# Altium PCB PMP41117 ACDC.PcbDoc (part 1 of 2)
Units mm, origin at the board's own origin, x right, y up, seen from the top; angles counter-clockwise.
Board outline 48.82 x 27.36 mm, 2 copper layers (Top Layer, Bottom Layer), stack 1.016 mm thick; 59 components, 38 nets, 168 pads, 388 vias.
Unrouted connection lines stored in the file: 2.
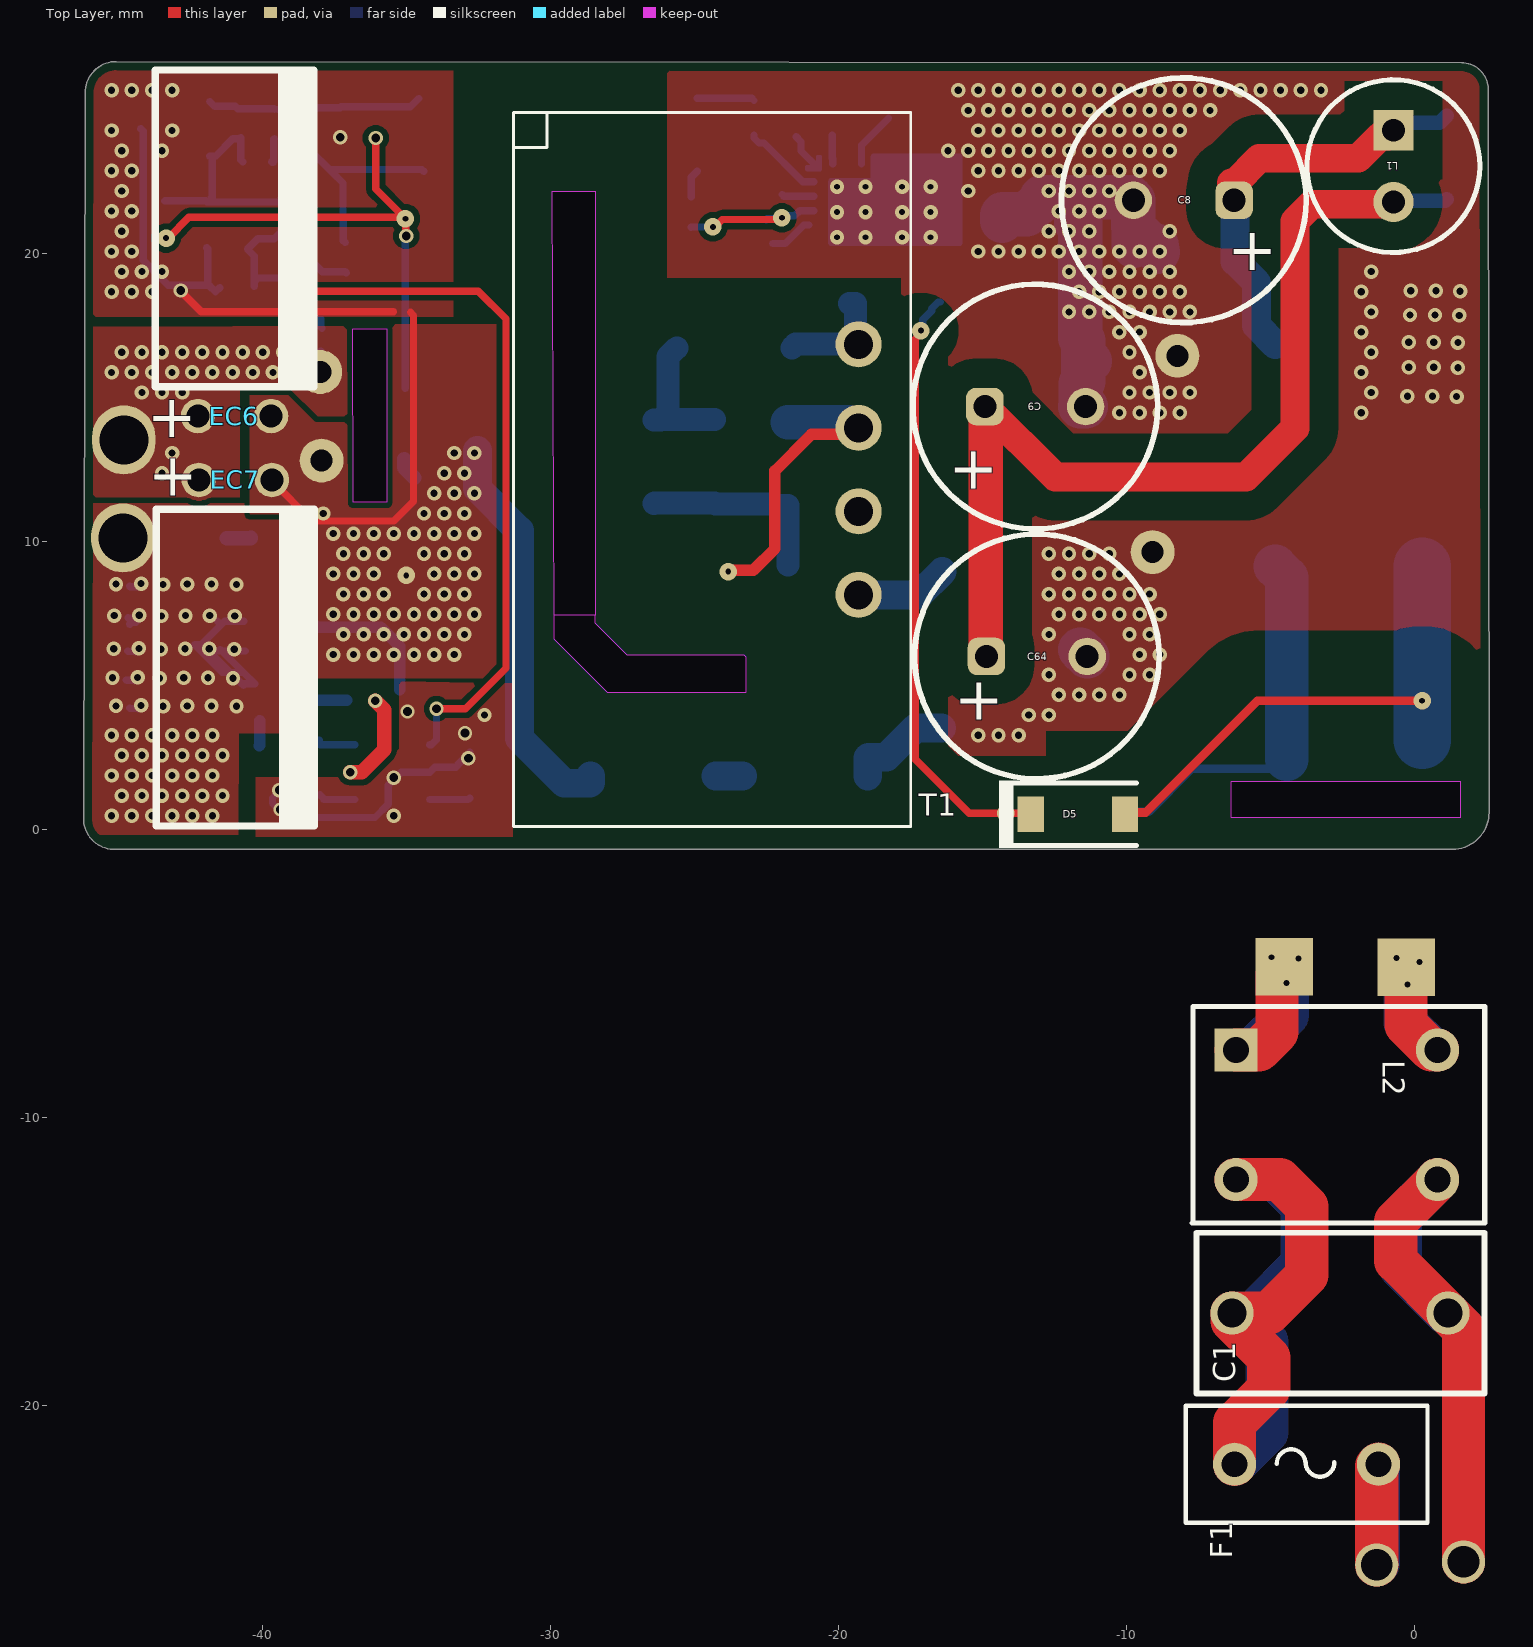
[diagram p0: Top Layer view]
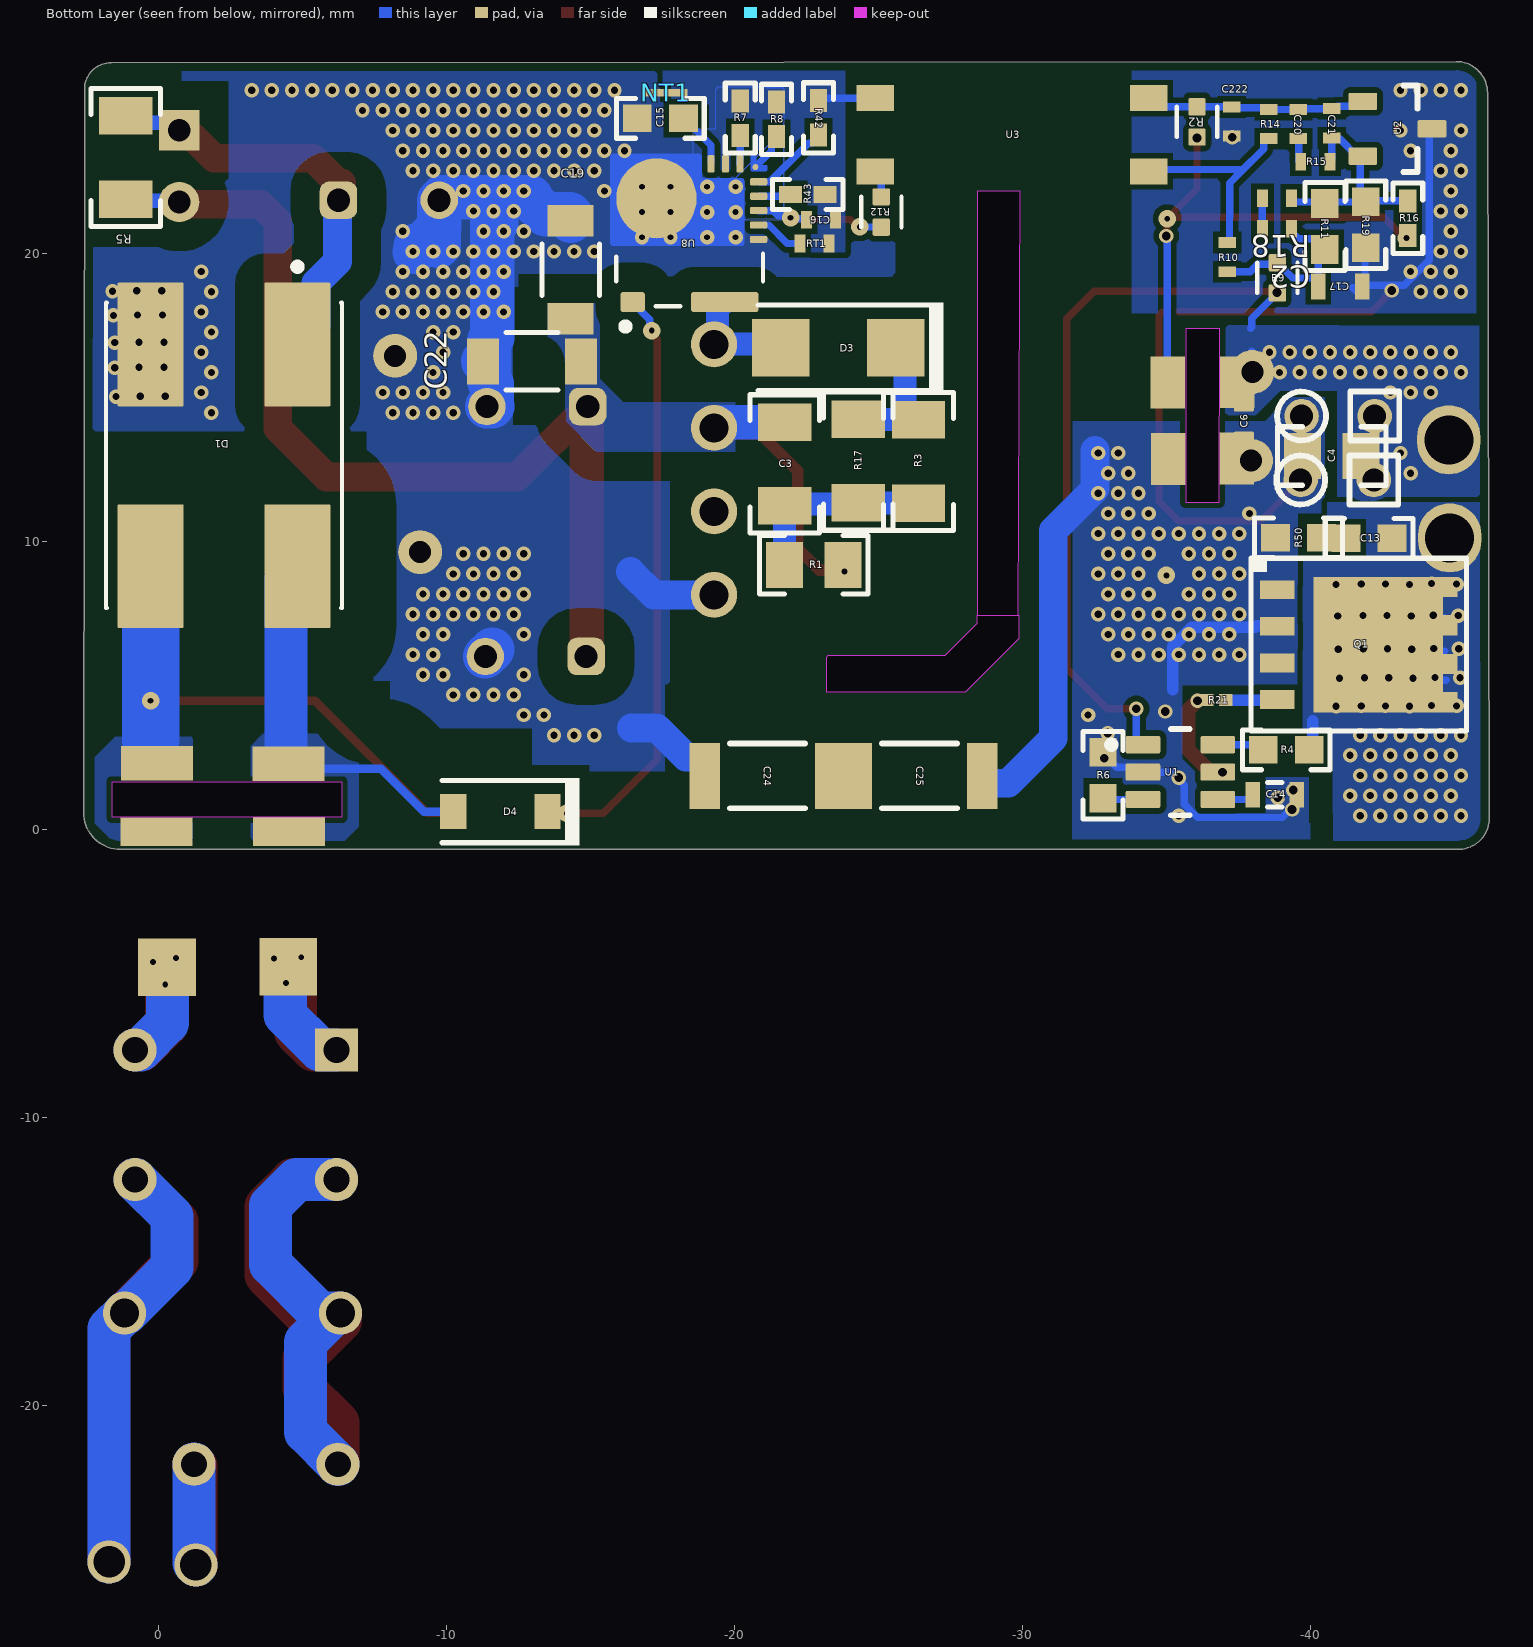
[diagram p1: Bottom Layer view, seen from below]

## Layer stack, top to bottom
Top Solder: solder mask 0.0102, Solder Resist, Dk 3.5
Top Layer: signal copper 0.0711
Dielectric1: core 0.8738, FR-4 High Tg, Dk 4.8
Bottom Layer: signal copper 0.0711
Bottom Solder: solder mask 0.0102, Solder Resist, Dk 3.5

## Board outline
-45.202,-0.676 cw(c-45.155,0.387) -46.208,0.234 -46.219,0.27 -46.164,25.595 cw(c-45.075,25.595) -45.075,26.684 1.643,26.644 cw(c1.643,25.723) 2.564,25.723 2.599,0.602 cw(c1.317,0.602) 1.318,-0.679 1.29,-0.679
cut-out: -6.376,1.665 -6.376,0.435 1.606,0.435 1.606,1.665
cut-out: -29.885,7.455 -29.885,6.63 -28.025,4.77 -23.21,4.77 -23.21,6 -23.27,6.06 -27.335,6.06 -28.445,7.17 -28.445,7.47
cut-out: -35.685,11.37 -36.846,11.37 -36.872,17.4 -35.685,17.4
cut-out: -28.445,7.455 -29.869,7.455 -29.931,22.185 -28.445,22.185 -28.445,19.53

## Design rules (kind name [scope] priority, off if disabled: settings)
AcuteAngle [All] p1: minimum=4.50000000000000E+0001 checktracksonly=FALSE
AssemblyTestPointUsage [All] p1: valid=2
BoardOutlineClearance BoardOutlineClearance_MountingHoles [OnCopper and InComponentClass('Mounting Holes')] p1: gap=0.3 ignorepadtopadclearanceinfootprint=FALSE
BoardOutlineClearance BoardOutlineClearance_Poly [OnCopper and IsPoly] p2: gap=0.3 ignorepadtopadclearanceinfootprint=FALSE
BoardOutlineClearance [OnCopper and Not InComponentClass('Logo') and not InComponentClass('FiducialMark') and not InRegion(1000,500,4000,800) and not InPoly] p3: gap=0.3 ignorepadtopadclearanceinfootprint=FALSE
Clearance Clearance_VAC_PGND [InNetClass('VAC') vs InNetClass('PGND')] p1: gap=2.286 ignorepadtopadclearanceinfootprint=TRUE
Clearance Clearance_HV_PGND [InNetClass('High Voltage') vs InNetClass('PGND')] p2: gap=1.016 ignorepadtopadclearanceinfootprint=TRUE
Clearance Clearance_SW_PGND [InNetClass('Switch Node') vs InNetClass('PGND')] p3: gap=0.864 ignorepadtopadclearanceinfootprint=TRUE
Clearance Clearance_AC_AC [InNetClass('VAC') vs InNetClass('VAC')] p4: gap=1 ignorepadtopadclearanceinfootprint=TRUE
Clearance Clearance_PGND_SGND [InNetClass('PGND') vs InNetClass('SGND')] p5: gap=4.064 ignorepadtopadclearanceinfootprint=TRUE
Clearance Clearance_HV_LV [InNetClass('High Voltage') vs InNetClass('Low Voltage')] p6: gap=0.864 ignorepadtopadclearanceinfootprint=TRUE
Clearance Clearance_SW_LV_1 [InNetClass('Switch Node') vs InNetClass('Low Voltage')] p7: gap=0.864 ignorepadtopadclearanceinfootprint=TRUE
Clearance Clearance_SW_HV [InNetClass('Switch Node') vs InNetClass('High Voltage')] p8: gap=0.864 ignorepadtopadclearanceinfootprint=TRUE
Clearance Clearance_1 [All] p9: gap=0.198 ignorepadtopadclearanceinfootprint=TRUE
Clearance Clearance_Keepouts [((IsTrack Or IsArc) And Not InPoly) And IsFree and IsKeepOut vs ((IsTrack Or IsArc) And Not InPoly) And IsFree and IsKeepOut] p10: gap=0 ignorepadtopadclearanceinfootprint=FALSE
Clearance Clearance_Poly [InPolygon] p11: gap=0.254 ignorepadtopadclearanceinfootprint=TRUE
Clearance Clearance_FiducialMark [IsKeepOut and InComponentClass('FiducialMark') vs IsPad and InComponentClass('FiducialMark')] p12: gap=0 ignorepadtopadclearanceinfootprint=FALSE
ComponentClearance ComponentClearance_MountingHoles_FiducialMarks [InComponentClass('Mounting Holes') vs InComponentClass('FiducialMark')] p1: gap=0.2 collisioncheckmode=3 verticalgap=0.2 showdistances=FALSE
ComponentClearance ComponentClearance_Shunt [InComponentClass('Header') vs InComponentClass('Shunt')] p2: gap=0 collisioncheckmode=3 verticalgap=0 showdistances=FALSE
ComponentClearance ComponentClearance_Logo [InComponentClass('Logo')] p3: gap=0.2 collisioncheckmode=3 verticalgap=0.2 showdistances=FALSE
ComponentClearance ComponentClearance_ScrewToNut [(HasFootprint('NY PMS 440 0025 PH')) vs (HasFootprint('Keystone_1902C'))] p4: gap=0.127 collisioncheckmode=3 verticalgap=0.254 showdistances=FALSE
ComponentClearance ComponentClearance_MountingHoles [InComponentClass('Mounting Holes')] p5: gap=1 collisioncheckmode=3 verticalgap=2540 showdistances=FALSE
ComponentClearance ComponentClearance_SmallPassives [HasFootprint('0201*') or HasFootprint('0402*') or HasFootprint('0508') or HasFootprint('0603*') or HasFootprint('0612') or HasFootprint('0805*') or HasFootprint('0815*') or HasFootprint('0830*') or HasFootprint('1206*') or HasFootprint('1210*') or HasFootprint('1808*') or HasFootprint('1812*') or HasFootprint('1825*') or HasFootprint('2010*') or HasFootprint('2220*') or HasFootprint('2225*') or HasFootprint('2512*') or HasFootprint('2728*') or HasFootprint('3518*') vs HasFootprint('0201*') or HasFootprint('0402*') or HasFootprint('0508') or HasFootprint('0603*') or HasFootprint('0612') or HasFootprint('0805*') or HasFootprint('0815*') or HasFootprint('0830*') or HasFootprint('1206*') or HasFootprint('1210*') or HasFootprint('1808*') or HasFootprint('1812*') or HasFootprint('1825*') or HasFootprint('2010*') or HasFootprint('2220*') or HasFootprint('2225*') or HasFootprint('2512*') or HasFootprint('2728*') or HasFootprint('3518*')] p6: gap=0.2 collisioncheckmode=3 verticalgap=0.2 showdistances=FALSE
ComponentClearance ComponentClearance_THtoSMT [IsThruComponent vs IsSMTComponent] p7: gap=0.2 collisioncheckmode=3 verticalgap=0.2 showdistances=FALSE
ComponentClearance ComponentClearance_THtoTH [IsThruComponent vs IsThruComponent] p8: gap=0.2 collisioncheckmode=3 verticalgap=0.2 showdistances=FALSE
ComponentClearance [All] p9: gap=0.1 collisioncheckmode=3 verticalgap=0.1 showdistances=FALSE
DiffPairsRouting DiffPair_DiffPairsRouting [All] p1: maxlimit=0.254 minlimit=0.254 mostfreqgap=0.254 toplayer_minwidth=0.254 toplayer_maxwidth=0.254 toplayer_prefwidth=0.254 bottomlayer_minwidth=0.254 bottomlayer_maxwidth=0.254 bottomlayer_prefwidth=0.254 filterlayerstackid={9F2BDCAB-BF4A-4FAE-9F57-695CEC5DA6CF} maxuncoupledlength=12.7
DiffPairsRouting DiffPair_DiffPairsRouting_1 [InDifferentialPair ('NewDifferentialPair1')] p2: maxlimit=0.203 minlimit=0.203 mostfreqgap=0.203 toplayer_minwidth=0.254 toplayer_maxwidth=0.254 toplayer_prefwidth=0.254 bottomlayer_minwidth=0.254 bottomlayer_maxwidth=0.254 bottomlayer_prefwidth=0.254 filterlayerstackid={9F2BDCAB-BF4A-4FAE-9F57-695CEC5DA6CF} maxuncoupledlength=12.7
DiffPairsRouting DiffPair_DiffPairsRouting_2 [InDifferentialPair ('NewDifferentialPair1')] p3: maxlimit=0.127 minlimit=0.127 mostfreqgap=0.127 toplayer_minwidth=0.254 toplayer_maxwidth=0.254 toplayer_prefwidth=0.254 bottomlayer_minwidth=0.254 bottomlayer_maxwidth=0.254 bottomlayer_prefwidth=0.254 filterlayerstackid={9F2BDCAB-BF4A-4FAE-9F57-695CEC5DA6CF} maxuncoupledlength=12.7
DiffPairsRouting DiffPair_DiffPairsRouting_3 [InDifferentialPair ('NewDifferentialPair1')] p4: maxlimit=0.178 minlimit=0.178 mostfreqgap=0.178 toplayer_minwidth=0.254 toplayer_maxwidth=0.254 toplayer_prefwidth=0.254 bottomlayer_minwidth=0.254 bottomlayer_maxwidth=0.254 bottomlayer_prefwidth=0.254 filterlayerstackid={9F2BDCAB-BF4A-4FAE-9F57-695CEC5DA6CF} maxuncoupledlength=12.7
DiffPairsRouting DiffPair_DiffPairsRouting_4 [InDifferentialPair ('NewDifferentialPair1')] p5: maxlimit=0.254 minlimit=0.254 mostfreqgap=0.254 toplayer_minwidth=0.381 toplayer_maxwidth=0.381 toplayer_prefwidth=0.381 bottomlayer_minwidth=0.381 bottomlayer_maxwidth=0.381 bottomlayer_prefwidth=0.381 filterlayerstackid={9F2BDCAB-BF4A-4FAE-9F57-695CEC5DA6CF} maxuncoupledlength=12.7
DiffPairsRouting DiffPair_DiffPairsRouting_5 [All] p6: maxlimit=0.254 minlimit=0.254 mostfreqgap=0.254 toplayer_minwidth=0.254 toplayer_maxwidth=0.254 toplayer_prefwidth=0.254 bottomlayer_minwidth=0.254 bottomlayer_maxwidth=0.254 bottomlayer_prefwidth=0.254 filterlayerstackid={9F2BDCAB-BF4A-4FAE-9F57-695CEC5DA6CF} maxuncoupledlength=12.7
DiffPairsRouting DiffPair_DiffPairsRouting_6 [All] p7: maxlimit=0.254 minlimit=0.254 mostfreqgap=0.254 toplayer_minwidth=0.254 toplayer_maxwidth=0.254 toplayer_prefwidth=0.254 bottomlayer_minwidth=0.254 bottomlayer_maxwidth=0.254 bottomlayer_prefwidth=0.254 filterlayerstackid={9F2BDCAB-BF4A-4FAE-9F57-695CEC5DA6CF} maxuncoupledlength=12.7
DiffPairsRouting DiffPair_DiffPairsRouting_7 [InDifferentialPair ('NewDifferentialPair2')] p8: maxlimit=0.254 minlimit=0.254 mostfreqgap=0.254 toplayer_minwidth=0.254 toplayer_maxwidth=0.254 toplayer_prefwidth=0.254 bottomlayer_minwidth=0.254 bottomlayer_maxwidth=0.254 bottomlayer_prefwidth=0.254 filterlayerstackid={9F2BDCAB-BF4A-4FAE-9F57-695CEC5DA6CF} maxuncoupledlength=12.7
DiffPairsRouting DiffPair_DiffPairsRouting_8 [InDifferentialPair ('NewDifferentialPair2')] p9: maxlimit=0.254 minlimit=0.254 mostfreqgap=0.254 toplayer_minwidth=0.381 toplayer_maxwidth=0.381 toplayer_prefwidth=0.381 bottomlayer_minwidth=0.381 bottomlayer_maxwidth=0.381 bottomlayer_prefwidth=0.381 filterlayerstackid={9F2BDCAB-BF4A-4FAE-9F57-695CEC5DA6CF} maxuncoupledlength=12.7
DiffPairsRouting DiffPair_DiffPairsRouting_9 [InDifferentialPair ('ISense_A')] p10: maxlimit=0.198 minlimit=0.198 mostfreqgap=0.198 toplayer_minwidth=0.254 toplayer_maxwidth=0.254 toplayer_prefwidth=0.254 bottomlayer_minwidth=0.254 bottomlayer_maxwidth=0.254 bottomlayer_prefwidth=0.254 filterlayerstackid={9F2BDCAB-BF4A-4FAE-9F57-695CEC5DA6CF} maxuncoupledlength=12.7
DiffPairsRouting DiffPair_DiffPairsRouting_10 [InDifferentialPair ('ISense_A')] p11: maxlimit=0.254 minlimit=0.254 mostfreqgap=0.254 toplayer_minwidth=0.381 toplayer_maxwidth=0.381 toplayer_prefwidth=0.381 bottomlayer_minwidth=0.381 bottomlayer_maxwidth=0.381 bottomlayer_prefwidth=0.381 filterlayerstackid={9F2BDCAB-BF4A-4FAE-9F57-695CEC5DA6CF} maxuncoupledlength=12.7
DiffPairsRouting DiffPair_DiffPairsRouting_11 [InDifferentialPair ('ISense_A')] p12: maxlimit=0.254 minlimit=0.254 mostfreqgap=0.254 toplayer_minwidth=0.381 toplayer_maxwidth=0.381 toplayer_prefwidth=0.381 bottomlayer_minwidth=0.381 bottomlayer_maxwidth=0.381 bottomlayer_prefwidth=0.381 filterlayerstackid={9F2BDCAB-BF4A-4FAE-9F57-695CEC5DA6CF} maxuncoupledlength=12.7
DiffPairsRouting DiffPair_ADiffPairsRouting [All] p13: maxlimit=0.198 minlimit=0.198 mostfreqgap=0.198 toplayer_minwidth=0.254 toplayer_maxwidth=0.254 toplayer_prefwidth=0.254 bottomlayer_minwidth=0.254 bottomlayer_maxwidth=0.254 bottomlayer_prefwidth=0.254 filterlayerstackid={9F2BDCAB-BF4A-4FAE-9F57-695CEC5DA6CF} maxuncoupledlength=12.7
DiffPairsRouting [All] p14: maxlimit=2.54 minlimit=0.254 mostfreqgap=0.254 toplayer_minwidth=0.381 toplayer_maxwidth=0.381 toplayer_prefwidth=0.381 bottomlayer_minwidth=0.381 bottomlayer_maxwidth=0.381 bottomlayer_prefwidth=0.381 maxuncoupledlength=25.4
FabricationTestPointUsage TestPointUsage [All] p1: valid=2 allowmultiple=FALSE
FabricationTestpoint Testpoint [All] p1: side=3 testpointundercomponent=TRUE minsize=1.016 maxsize=2.54 preferedsize=1.524 minholesize=0 maxholesize=1.016 preferedholesize=0.813 testpointgrid=0.025 allowsidetop=TRUE allowsidebottom=TRUE usegrid=TRUE gridtolerance=0
FanoutControl Fanout_LCC [IsLCC] p1: bgadir=Out bgaviamode=Centered fanoutstyle=Auto fanoutdirection=Alternating viagrid=0.025 // Fanout_LCC (Default Rule)
FanoutControl Fanout_BGA [IsBGA] p2: bgadir=Out bgaviamode=Centered fanoutstyle=Auto fanoutdirection=Alternating viagrid=0.025 // Fanout_BGA (Default Rule)
HoleSize [All] p1: absolutevalues=TRUE maxlimit=6.375 minlimit=0.2 maxpercent=80.000 minpercent=20.000
MatchedLengths DiffPair_MatchedLengths [All] p1: tolerance=25.4 checknetsindiffpair=FALSE checkdiffpairvsdiffpair=TRUE checkxsignals=TRUE checkothers=TRUE
MatchedLengths DiffPair_MatchedLengths_1 [InDifferentialPair ('NewDifferentialPair1')] p2: tolerance=25.4 checknetsindiffpair=FALSE checkdiffpairvsdiffpair=TRUE checkxsignals=TRUE checkothers=TRUE
MatchedLengths DiffPair_MatchedLengths_2 [InDifferentialPair ('NewDifferentialPair1')] p3: tolerance=25.4 checknetsindiffpair=FALSE checkdiffpairvsdiffpair=TRUE checkxsignals=TRUE checkothers=TRUE
MatchedLengths DiffPair_MatchedLengths_3 [InDifferentialPair ('NewDifferentialPair1')] p4: tolerance=25.4 checknetsindiffpair=FALSE checkdiffpairvsdiffpair=TRUE checkxsignals=TRUE checkothers=TRUE
MatchedLengths DiffPair_MatchedLengths_4 [InDifferentialPair ('NewDifferentialPair1')] p5: tolerance=25.4 checknetsindiffpair=FALSE checkdiffpairvsdiffpair=TRUE checkxsignals=TRUE checkothers=TRUE
MatchedLengths DiffPair_MatchedLengths_5 [All] p6: tolerance=25.4 checknetsindiffpair=FALSE checkdiffpairvsdiffpair=TRUE checkxsignals=TRUE checkothers=TRUE
MatchedLengths DiffPair_MatchedLengths_6 [All] p7: tolerance=25.4 checknetsindiffpair=FALSE checkdiffpairvsdiffpair=TRUE checkxsignals=TRUE checkothers=TRUE
MatchedLengths DiffPair_MatchedLengths_7 [InDifferentialPair ('NewDifferentialPair2')] p8: tolerance=25.4 checknetsindiffpair=FALSE checkdiffpairvsdiffpair=TRUE checkxsignals=TRUE checkothers=TRUE
MatchedLengths DiffPair_MatchedLengths_8 [InDifferentialPair ('NewDifferentialPair2')] p9: tolerance=25.4 checknetsindiffpair=FALSE checkdiffpairvsdiffpair=TRUE checkxsignals=TRUE checkothers=TRUE
MatchedLengths DiffPair_MatchedLengths_9 [InDifferentialPair ('ISense_A')] p10: tolerance=25.4 checknetsindiffpair=FALSE checkdiffpairvsdiffpair=TRUE checkxsignals=TRUE checkothers=TRUE
MatchedLengths DiffPair_MatchedLengths_10 [InDifferentialPair ('ISense_A')] p11: tolerance=25.4 checknetsindiffpair=FALSE checkdiffpairvsdiffpair=TRUE checkxsignals=TRUE checkothers=TRUE
MatchedLengths DiffPair_MatchedLengths_11 [InDifferentialPair ('ISense_A')] p12: tolerance=25.4 checknetsindiffpair=FALSE checkdiffpairvsdiffpair=TRUE checkxsignals=TRUE checkothers=TRUE
MatchedLengths DiffPair_AMatchedLengths [All] p13: tolerance=25.4 checknetsindiffpair=FALSE checkdiffpairvsdiffpair=TRUE checkxsignals=TRUE checkothers=TRUE
MinimumAnnularRing MinimumAnnularRing_ThermalPadVias [IsVia and InAnyComponent] p1: minimumring=0.15
MinimumAnnularRing [All] p2: minimumring=0.2
MinimumSolderMaskSliver MinimumSolderMaskSliver_Logo [InComponentClass('Logo') vs InComponentClass('Logo')] p1: minsoldermaskwidth=0.018
MinimumSolderMaskSliver [All] p2: minsoldermaskwidth=0.1
PlaneConnect [All] p1: planeconnectstyle=Relief reliefexpansion=0.254 reliefentries=4 reliefconductorwidth=0.254 reliefairgap=0.254
PolygonConnect [All] p1: connectstyle=Direct reliefconductorwidth=0.254 reliefentries=4 polygonreliefangle="90 Angle" airgapwidth=0
RoutingVias ThermalPadVias [IsVia and InAnyComponent] p1: holewidth=0.2 width=0.5 viastyle="Through Hole" minholewidth=0.2 minwidth=0.5 maxholewidth=0.33 maxwidth=0.6
RoutingVias [All] p2: holewidth=0.406 width=0.864 viastyle="Through Hole" minholewidth=0.2 minwidth=0.61 maxholewidth=1.016 maxwidth=1.651
SilkToSilkClearance SilkToSilkClearance_Pb-FreeLogo [(HasFootprint('Pb-Free_Overlay_Medium') OR HasFootprint('Pb-Free_Overlay_Small')) vs (HasFootprint('Pb-Free_Overlay_Medium') OR HasFootprint('Pb-Free_Overlay_Small'))] p1: silktosilkclearance=0
SilkToSilkClearance [All] p2: silktosilkclearance=0.1
SilkToSolderMaskClearance SilkToComponentPadClearance [(IsPad or IsFill or IsRegion) and InAnycomponent] p1: minsilkscreentomaskgap=0.127 clearancetoexposedcopper=TRUE
SilkToSolderMaskClearance "Silk to Solder Mask Opening" [All] p2: minsilkscreentomaskgap=0.1 clearancetoexposedcopper=FALSE
SolderMaskExpansion [All] p1: expansion=0.05 istentingtop=FALSE
UnRoutedNet [All] p1: checkbadconnections=TRUE
Width [All] p1: maxlimit=2.54 minlimit=0.152 preferedwidth=0.254 checkconnectedcopper=TRUE
17 further rules are at their usual default settings.

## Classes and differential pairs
net class "Low Voltage": APGND FB_ACDC NetC2_1 NetC2_2 NetC15_1 NetC16_1 NetC20_1 NetC20_2 NetC21_1 NetD3_2 NetD4_1 NetR7_2 NetR8_2 NetR10_1 NetR12_2 NetR42_2 NetR43_2 NetRT1_2 NetU2_2 NetU2_8 NetU2_9 NetU2_16 NetU2_17 NetU2_18 NetU2_19 NetU2_20 NetU2_21 NetU7_8 PGND SGND VO_ACDC
net class VAC: LINE NetC1_2 NetD1_2 NetD1_3 Neture
net class "Switch Node": NetD3_2
net class SGND: SGND VO_ACDC VSR_SW
net class PGND: PGND
net class "High Voltage": NetC3_2 NetC8_1 NetD4_1

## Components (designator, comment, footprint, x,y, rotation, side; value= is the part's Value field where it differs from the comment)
C1 "MX2334KQ3B83YB2000R" "X CAP small form 7_10_8" 1.17,-16.785 r180 top value=330nF
C2 "CGA2B3X7R1H333K050BB" 0402S -38.85,20.88 r0 bottom value=0.033uF
C3 "GRM31BR72J102KW01L" 1206 -21.758,12.71 r90 bottom value=1000pF
C4 "TMK212BBJ106KG-T" 0805_HV -40.753,12.982 r0 bottom value=10uF
C6 "CGA3E2X8R1E104K080AD" FP-CGA3E2X8R1E104K080AD_0603-MFG -37.701,14.178 r270 bottom value=100nF
C8 "33u/400V" WCAP-ATG5_D8H16 -8.005,21.865 r0 top value=33uF
C9 "33u/400V" WCAP-ATG5_D8H16 -13.163,14.699 r180 top value=33uF
C13 "GRM1885C2A221JA01D" 0603 -42.05,10.125 r0 bottom value=220pF
C14 "CGA3E1X7R1E105K080AC" 0603S -38.771,1.223 r180 bottom value=1uF
C15 "CL10A226MP8NUNE" 0603 -17.435,24.712 r0 bottom value=22uF
C16 "GRM155R71H331KA01D" 0402S -23.018,21.186 r180 bottom value=330pF
C17 "C1608X7R1E105K080AB" 0603S -41.052,18.87 r0 bottom value=1uF
C19 "C3216X7T2W104M160AA" 1206_180 -14.32,19.455 r90 bottom value=0.1uF
C20 "GRM155R71H472KA01D" 0402S -39.585,24.51 r90 bottom value=4700pF
C21 "885012205055" 0402S -40.755,24.54 r90 bottom value=100pF
C22 "C3216X7T2W104M160AA" 1206_180 -12.977,16.269 r0 bottom value=0.1uF
C24 "8853522100131" WCAP-CSSA_1808_L4.5W2H2 -21.156,1.871 r180 bottom
C25 "8853522100131" WCAP-CSSA_1808_L4.5W2H2 -26.436,1.871 r180 bottom
C64 "33u/400V" WCAP-ATG5_D8H16 -13.109,6.021 r180 top value=33uF
C222 "885012205055" 0402S -37.275,24.6 r90 bottom value=100pF
D1 "Z4DGP406L-HF" FP-Z4DGP406L-HF_SMT_8MM1_10MM5-MFG -2.28,13.005 r180 bottom
D3 "MRA4007T3G" SMA -23.614,16.74 r0 bottom value=1000V
D4 "ES1JFL" SOD-123 -11.88,0.63 r0 bottom value=600V
D5 "ES1JFL" SOD-123 -11.685,0.54 r0 top value=600V
EC6 "ECAP_LAYDOWN" CE05.5P254L11 -42.245,14.37 r0 top value=470uF
EC7 "ECAP_LAYDOWN" CE05.5P254L11 -42.215,12.15 r0 top value=470uF
F1 "RSTA 3.15-BULK" FUSE -6.24,-22.035 r180 top
L1 "33uH" WE-TI_5075 -0.725,23.051 r270 top
L2 "CMP-0088773-1" "LT 8*5 with pad" -6.19,-7.65 r0 top value=22uH
NT1 "Net-Tie" Net-Tie_10milWide_30milLong -17.621,25.599 r180 bottom net-tie
Q1 "ISC030N10NM6" PG-TDSON-8 -41.69,6.43 r180 bottom value=150V
R1 "CRCW0805470KJNEA" 0805_HV -22.763,9.201 r180 bottom value=470k
R2 "CRCW04020000Z0EDHP" FP-CRCW04020000Z0EDHP_0402-MFG -36.075,24.585 r90 bottom value=0
R3 "RC1206FR-0730RL" 1206 -26.401,12.789 r270 bottom value=30.0
R4 "RC0603FR-07300RL" 0603 -39.174,2.777 r0 bottom value=300
R5 "CRCW12064K70JNEA" 1206 1.133,23.352 r270 bottom value=4.7k
R6 "CRCW060347K0FKEA" 0603 -32.807,1.897 r270 bottom value=47.0k
R7 "CRCW040228K7FKED" 0402 -20.21,24.72 r270 bottom value=28.7k
R8 "CRCW040228K7FKED" 0402 -21.47,24.675 r270 bottom value=28.7k
R9 "CRCW04020000Z0EDHP" FP-CRCW04020000Z0EDHP_0402-MFG -38.865,19.17 r270 bottom value=0
R10 "CRCW04023K01FKED" 0402S -37.125,19.89 r270 bottom value=3.01k
R11 "RT0603DRE07105KL" 0603 -40.515,20.955 r270 bottom value=105k
R12 "CRCW04020000Z0EDHP" FP-CRCW04020000Z0EDHP_0402-MFG -25.108,21.457 r90 bottom value=0
R14 "CRCW040215K0FKED" 0402S -38.565,24.51 r270 bottom value=15.0k
R15 "RC0402FR-074K7L" 0402S -40.185,23.205 r180 bottom value=4.70k
R16 "CRCW04021R00JNED" 0402 -43.395,21.24 r270 bottom value=1.0
R17 "RC1206FR-0730RL" 1206 -24.306,12.805 r270 bottom value=30.0
R18 "CRCW04021K20JNED" 0402S -38.85,21.93 r0 bottom value=1.2k
R19 "RT0603DRE0775KL" 0603 -41.94,21.015 r90 bottom value=75.0k
R21 "CRCW02010000Z0ED" 0201 -36.745,4.505 r0 bottom value=0
R42 "CRCW040211K5FKED" 0402 -22.93,24.728 r270 bottom value=11.5k
R43 "CRCW040225K5FKED" 0402 -22.553,22.065 r0 bottom value=25.5k
R50 "CRCW060312R0JNEA" 0603 -39.6,10.14 r180 bottom value=12
RT1 "NCP15WF104F03RC" 0402S -22.792,20.363 r0 bottom value=100k
T1 "ATQ23_14 4_4 Pin" "ATQ23.9_13.8_REMOVE FLYWIRE" -19.3,12.51 r0 top
U1 "MP6908GJ-Z" FP-MP6908GJ-Z_TSOT23-6-MFG -35.498,2.005 r180 bottom
U2 "ATL431AIDBZR" DBZ0003A_N -43.033,24.346 r180 bottom
U3 "VOL618A-2T" SOP254P1020X230-4 -29.655,24.14 r0 bottom
U8 "UCG28826" REZ0012A-MFG -18.448,20.73 r90 bottom

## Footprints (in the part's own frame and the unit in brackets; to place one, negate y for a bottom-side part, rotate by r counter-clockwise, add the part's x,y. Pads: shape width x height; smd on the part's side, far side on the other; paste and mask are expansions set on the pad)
0201 [mm] "Data from Kemet datasheet CC101_COM dated 7/28/11"
  rect 0.46x0.42 smd mask+0.048: 1(-0.33,0) 2(0.33,0)
  body extent -0.31,-0.16 0.31,0.16, height 0.26
0402 [mm] "0402 from SM-752 data"
  rect 0.8x0.6 smd: 1(-0.6,0) 2(0.6,0)
  silkscreen extent -1.22,-0.52 1.22,0.52, body extent -0.55,-0.3 0.55,0.3, height 0.6
0402S [mil] "Based on C0402S footprint from PADS legacy"
  rect 15x24 smd: 1(-20,0) 2(20,0)
  body extent -22,-12 22,12, height 24
0603 [mm] "0603 from SM-752 data"
  rect 1x0.95 smd: 1(-0.8,0) 2(0.8,0)
  silkscreen extent -1.52,-0.69 1.52,0.69, body extent -0.87,-0.47 0.87,0.47, height 1
0603S [mil]
  rect 20x35 smd: 1(-30,0) 2(30,0)
  silkscreen extent -10,-17 10,17, body extent -34,-19 34,19, height 39
0805_HV [mil] "0805 with 30mil clearance between pads"
  rect 50x63 smd: 1(-40,0) 2(40,0)
  silkscreen extent -74,-40 74,40, body extent -43,-29 43,29, height 57
1206 [mm] "1206 from SM-752 data"
  rect 1.3x1.85 smd: 1(-1.45,0) 2(1.45,0)
  silkscreen extent -2.4,-1.21 2.4,1.21, body extent -1.7,-0.9 1.7,0.9, height 1.35
1206_180 [mm] "1206_180"
  rect 1.1x1.6 smd: 1(-1.7,0) 2(1.7,0)
  silkscreen extent -0.9,-1 0.9,1, body extent -1.75,-0.95 1.75,0.95, height 1.8
"ATQ23.9_13.8_REMOVE FLYWIRE" [mm]
  round 1.6 hole 1: 1(0,-4.35) 2(0,-1.45) 3(0,1.45) 4(0,4.35)
  silkscreen extent -11.99,-12.4 1.81,12.4
CE05.5P254L11 [mm]
  round 1.2 hole 0.8: 1(0,0) 2(2.54,0)
  silkscreen extent -1.48,1.02 4.02,12.02
DBZ0003A_N [mm] "SOT23, 3-Leads, Body 2.9x1.3mm, Pitch 0.95mm, Lead Span 2.4mm, IPC Medium Density"
  rrect17% 1x0.6 smd: 1(-1.2,0.95) 2(-1.2,-0.95) 3(1.2,0)
  silkscreen extent 0.2,-1.5 0.7,1.5, body extent -1.26,-1.46 1.26,1.46, height 0.98
FP-CGA3E2X8R1E104K080AD_0603-MFG [mm]
  rrect14% 0.7x0.7 smd paste+0 mask+0: 1(-0.7,0) 2(0.7,0)
  body extent -0.8,-0.4 0.8,0.4, height 0.95
FP-CRCW04020000Z0EDHP_0402-MFG [mm]
  rrect17% 0.6x0.6 smd paste+0 mask+0: 1(-0.525,0) 2(0.525,0)
  silkscreen extent -0.53,-0.7 0.53,0.7, body extent -0.5,-0.25 0.5,0.25, height 0.4
FP-MP6908GJ-Z_TSOT23-6-MFG [mm]
  rrect17% 1.2x0.6 smd paste+0 mask+0: 1(-1.3,0.95) 2(-1.3,0) 3(-1.3,-0.95) 4(1.3,-0.95) 5(1.3,0) 6(1.3,0.95)
  silkscreen extent -2.53,-1.5 0.33,1.5, body extent -1.4,-1.45 1.4,1.45, height 1
FP-Z4DGP406L-HF_SMT_8MM1_10MM5-MFG [mm]
  rrect4% 2.3x4.3 smd paste+0 mask+0: 1(2.55,3.85) 2(2.55,-3.85) 3(-2.55,-3.85) 4(-2.55,3.85)
  silkscreen extent -4.1,-5.3 4.1,6.67, body extent -4.05,-5.25 4.05,5.25, height 1.45
FUSE [mm]
  round 1.5 hole 0.9: 1(0,0) 2(-5,0)
  silkscreen extent -6.7,-2.03 1.7,2.03, body extent -6.7,-2.03 1.7,2.03, height 5
"LT 8*5 with pad" [mm] "WE-CMB Series Size XS"
  rect 1.5x1.5 hole 0.9: 1(0,0)
  round 1.5 hole 0.9: 2(7,0) 3(7,-4.5) 4(0,-4.5)
  silkscreen extent -1.52,-6 8.64,1.52
Net-Tie_10milWide_30milLong [mil] "10mil net tie, no solder mask opening, no solder paste"
  rect 30x10 smd paste-5 mask-5: 1(-15,0) 2(15,0)
PG-TDSON-8 [mm] "Infineon recommended land pattern"
  rect 1.2x0.65 smd: 1(-2.825,1.905) 2(-2.825,0.635) 3(-2.825,-0.635) 4(-2.825,-1.905)
  rect 0.5x0.7 smd: 5(3.175,-2) 6(3.175,-0.675) 7(3.175,0.675) 8(3.175,2)
  rect 4.5x4.7 smd paste-2.25: 9(0.675,0)
  silkscreen extent -3.74,-3 3.74,3, body extent -3.18,-2.89 3.18,2.9, height 1.1
REZ0012A-MFG [mm]
  rrect29% 0.7x0.85 smd paste-1000 mask-1000: 1(-2.4,1.975)
  rrect29% 0.7x2.35 smd paste-1000 mask-1000: 2(-2.4,-1.225)
  rrect40% 0.25x0.6 smd paste+0 mask+0: 3(-0.225,-2.4) 4(0.275,-2.4) 5(0.775,-2.4) 6(1.275,-2.4) 7(1.775,-2.4)
  round 0.203 smd paste+0 mask+0: 8(2.288,-2.288)
  rrect40% 0.6x0.25 smd paste+0 mask+0: 9(2.4,-1.75) 10(2.4,-1.25) 11(2.4,-0.75)
  round 2.788 smd paste-1000 mask-1000: 12(1.199,1.148)
  Top Layer region: 2.2,-2.7 2.175,-2.693 2.157,-2.675 2.15,-2.65 2.15,-2.65 2.15,-2.175 2.154,-2.156 2.165,-2.14 2.181,-2.129 2.2,-2.125 2.2,-2.125 2.65,-2.125 2.669,-2.129 2.685,-2.14 2.696,-2.156 2.7,-2.175 2.7,-2.175 2.7,-2.275 2.693,-2.3 2.675,-2.318 2.65,-2.325 2.65,-2.325 2.45,-2.325 2.412,-2.333 2.379,-2.354 2.358,-2.387 2.35,-2.425 2.35,-2.425 2.35,-2.65 2.343,-2.675 2.325,-2.693 2.3,-2.7 2.3,-2.7
  Top Layer region: -0.45,2.65 -0.437,2.7 -0.4,2.737 -0.35,2.75 -0.35,2.75 2.648,2.75 2.698,2.737 2.735,2.7 2.748,2.65 2.748,2.65 2.748,-0.325 2.735,-0.375 2.698,-0.412 2.648,-0.425 2.648,-0.425 1.95,-0.425 1.931,-0.429 1.915,-0.44 1.904,-0.456 1.9,-0.475 1.9,-0.475 1.9,-1.8 1.887,-1.85 1.85,-1.887 1.8,-1.9 1.8,-1.9 -0.35,-1.9 -0.4,-1.887 -0.437,-1.85 -0.45,-1.8 -0.45,-1.8
  silkscreen extent -3.37,-2.55 -0.72,2.55, body extent -2.5,-2.5 2.5,2.5, height 1
SMA [mm] "Molded Diode, 2-Leads, Body 4.3x2.6mm, IPC Medium Density, based on OnSemi component dimensions and land pattern"
  rect 2x2 smd: 1(-2,0) 2(2,0)
  silkscreen extent -3.66,-1.58 2.79,1.57, body extent -2.6,-1.3 2.6,1.3, height 2.42
SOD-123 [mm] "On Semi recommended land pattern"
  rect 0.915x1.22 smd: 1(-1.637,0) 2(1.637,0)
  silkscreen extent -2.74,-1.17 2.03,1.17, body extent -1.93,-0.9 1.93,0.9, height 1.35
SOP254P1020X230-4 [mm] "VISHAY"
  rect 1.3x0.9 smd: 1(-4.75,1.27) 2(-4.75,-1.27) 3(4.75,-1.27) 4(4.75,1.27)
  body extent -3.85,-2.05 3.85,2.05, height 2.02
WCAP-ATG5_D8H16 [mm] "Aluminum Electrolytic Capacitors, 8x16mm"
  rrect50% 1.3x1.3 hole 0.8: 1(1.75,0)
  round 1.3 hole 0.8: 2(-1.75,0)
  silkscreen extent -4.25,-4.25 4.25,4.25, body extent -3.99,-4 4,4, height 16.31
WCAP-CSSA_1808_L4.5W2H2 [mm] "Ceramic Capacitors, body 4.50x2.00mm"
  rect 1.05x2.3 smd: 1(-2.175,0) 2(2.175,0)
  silkscreen extent -1.3,-1.12 1.3,1.12, body extent -2.25,-1 2.25,1, height 2
WE-TI_5075 [mm] "Wurth WE-TI 5075"
  rect 1.4x1.4 hole 0.787: 1(-1.25,0)
  round 1.4 hole 0.787: 2(1.25,0)
  silkscreen extent -3,-3 3,3, body extent -3,-3 3,3, height 8.5
"X CAP small form 7_10_8" [mm]
  round 1.5 hole 1: 1(0,0) 2(7.5,0)
  silkscreen extent -1.27,-2.79 8.73,2.79

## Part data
C1: library part CMP-0112463-1, "X2 Film Capacitor, THT, 330nF, 275V", Capacitance Tolerance=+/-10%, Insulation Resistance=30000MOhm, Manufacturer="DongGuan Chengxi", Operating Temperature Max=105°C, Operating Temperature Min=-40°C, Rate of Voltage Rise=300V/us, Rated Voltage (AC)=275V
C2: library part CMP-0006329-2, "CAP, CERM, 0.033 uF, 50 V, +/- 10%, X7R, AEC-Q200 Grade 1, 0402", Cap_Case=0402, Manufacturer=TDK, Supplier Part Number 1=445-6896-1-ND, TempCo=X7R, Tolerance_%=10%, Value1="0.098477 ohm", Value2=50V, ValueDisplayed=0.033uF
C3: library part CMP-0008909-2, "CAP, CERM, 1000 pF, 630 V, +/- 10%, X7R, 1206", Cap_Case=1206, Manufacturer=MuRata, Supplier Part Number 1=490-3506-1-ND, TempCo=X7R, Tolerance_%=10%, Value1=Unknown, Value2=630V, ValueDisplayed=1000pF
C4: library part CMP-0008414-2, "CAP, CERM, 10 uF, 25 V, +/- 10%, X5R, 0805", Cap_Case=0805, Manufacturer="Taiyo Yuden", Supplier Part Number 1=587-2985-1-ND, TempCo=X5R, Tolerance_%=10%, Value1=Unknown, Value2=25V, ValueDisplayed=10uF
C6: library part CMP-0086497-1, "0.1µF ±10% 25V Ceramic Capacitor X8R 0603 (1608 Metric)", Manufacturer="TDK Corporation", TempCo=15%, Tolerance_%=10%
C8 C9 C64: library part CMP-0116785-1, "KCMD2002G330MF Aluminum Electrolytic Capacitor, Radial, THT, D8 x H20mm, 33µF, 400V", Capacitance Tolerance=+0%/-40%, Case/Size Code="D8 x H20mm", Leakage Current=264uA, Manufacturer=Yongming, Manufacturer Part Number=KCMD2002G330MF, Operating Temperature Max=105°C, Operating Temperature Min=-25°C, Rated Voltage (DC)=400V, Ripple Current=200mA
C13: library part CMP-0007256-4, "CAP, CERM, 220 pF, 100 V, +/- 5%, C0G/NP0, 0603", Cap_Case=0603, Manufacturer=MuRata, Supplier Part Number 1=490-1359-1-ND, TempCo=C0G/NP0, Tolerance_%=5%, Value1=Unknown, Value2=100V, ValueDisplayed=220pF
C14: library part CMP-0076705-1, "CAP, CERM, 1 µF, 25 V,+/- 10%, X7R, AEC-Q200 Grade 1, 0603", Cap_Case=1.6x0.8x0.8mm, Manufacturer=TDK, Supplier Part Number 1=445-6931-1-ND, TempCo=X7R, Tolerance_%=10%, Value2=25V, ValueDisplayed=1µF
C15: library part CMP-0007108-2, "CAP, CERM, 22 uF, 10 V, +/- 20%, X5R, 0603", Cap_Case=0603, Manufacturer="Samsung Electro-Mechanics", TempCo=X5R, Tolerance_%=20%, Value1=Unknown, Value2=10V, ValueDisplayed=22uF
C16: library part CMP-0006687-2, "CAP, CERM, 330 pF, 50 V, +/- 10%, X7R, 0402", Cap_Case=0402, Manufacturer=MuRata, Supplier Part Number 1=490-3247-1-ND, TempCo=X7R, Tolerance_%=10%, Value1=Unknown, Value2=50V, ValueDisplayed=330pF
C17: library part CMP-0007040-4, "CAP, CERM, 1 µF, 25 V, +/- 10%, X7R, 0603", Cap_Case=0603, Manufacturer=TDK, Supplier Part Number 1=445-5956-1-ND, TempCo=X7R, Tolerance_%=10%, Value1=Unknown, Value2=25V, ValueDisplayed=1uF
C19 C22: library part CMP-0008729-1, "CAP, CERM, 0.1 uF, 450 V, +/- 20%, X7T, 1206", Cap_Case=1206, Manufacturer=TDK, Supplier Part Number 1=445-14838-1-ND, TempCo=X7T, Tolerance_%=20%, Value1=Unknown, Value2=450V, ValueDisplayed=0.1uF
C20: library part CMP-0006692-2, "CAP, CERM, 4700 pF, 50 V, +/- 10%, X7R, 0402", Cap_Case=0402, Manufacturer=MuRata, Supplier Part Number 1=490-1308-1-ND, TempCo=X7R, Tolerance_%=10%, Value1=Unknown, Value2=50V, ValueDisplayed=4700pF
C21 C222: library part CMP-0006230-2, "CAP, CERM, 100 pF, 50 V, +/- 10%, X7R, 0402", Cap_Case=0402, Manufacturer="Wurth Elektronik", Supplier Part Number 1=732-7550-1-ND, TempCo=X7R, Tolerance_%=10%, Value1=Unknown, Value2=50V, ValueDisplayed=100pF
C24 C25: library part CMP-0119859-1, "WCAP-CSSA Multilayer Ceramic Chip Safety Capacitor, size 1808, X7R Class II, 1nF, 250VAC", Capacitance Tolerance=+/-10%, Case/Size Code=1808, Impulse Voltage=5000VDC, Insulation Resistance=10GOhm, Manufacturer="Wurth Elektronik", Operating Temperature Max=125°C, Operating Temperature Min=-55°C, Rated Voltage (AC)=250V
D1: library part CMP-0120719-1, "Bridge Rectifier Single Phase Standard 600 V Surface Mount Z4-D", Digikey Part Number=641-1502-1-ND, Forward Current=4A, Manufacturer=Comchip, Max Surge Forward Current=150A, Mouser Part Number=750-Z4DGP406L-HF, Operating Temperature Range="-55°C to +175°C", Peak Reverse Current=0.08uA, ValueDisplayed=45pF
D3: library part CMP-0077082-2, "Diode, Standard Recovery Rectifier, 1000 V, 1 A, AEC-Q101, SMA", Manufacturer="ON Semiconductor", Value1=1A, Value2=1.1V
D4 D5: library part CMP-0029032-2, "Diode, Switching, 600 V, 1 A, SOD-123", Manufacturer="ON Semiconductor", Supplier Part Number 1=ES1JFLDKR-ND, Value1=1A, Value2=1V
EC6 EC7: "25V/470uF D5.5*11mm", Manufacturer=Yongming, PartNumber=NPXC1001E471MJTM, Voltage=25V
F1: library part Fuse, "Fuse, 3.15 A, 250 VAC, 63 VDC, TH", Irating_A=3.15A, Manufacturer="Bel Fuse", Supplier Part Number 1=507-1861-ND
L1: library part CMP-0064517-1, "Inductor, Unshielded Drum Core, 6*12mm, 33 uH, 2 A, TH RL0612-330K-HF", Manufacturer="Huizhou Deli Electronics", PartNumber=RL0612-330K-HF, Supplier Part Number 1=732-2570-ND, Value1="0.102 ohm", Value2=1.7A
L2: "8*5mm CM choke 22uH, 0.5 wire* 6T, TCB8X4X3-8R0MINX2-JS-HF", Manufacturer="Huizhou Deli Electronics", Operating Temperature Range="-40°C to +125°C", Part Number=TCB8X4X3-8R0MINX2-JS-HF, Test Frequency=10kHz, Tolerance_%=30%
NT1: library part CMP-0078142-6, "Single point connection between nets.", Manufacturer=N/A
Q1: library part CMP-0001046-2, "MOSFET, N-CH, 100 V, 3.3mR, PG-TDSON-8", Alternate Manufacturer=None, Manufacturer="Infineon Technologies", Supplier Part Number 1=BSC093N15NS5ATMA1CT-ND, Value2="33 nC"
R1: library part CMP-0020554-3, "RES, 470 k, 5%, 0.125 W, AEC-Q200 Grade 0, 0805", Manufacturer=Vishay-Dale, Power_W=125mW, Supplier Part Number 1=541-470KACT-ND, TempCo="200 ppm/C", Tolerance_%=5%, Value2=0.125W, Value_Code=470k
R2 R9 R12: library part CMP-0001606-1, "RES Thick Film, 0Ω, 0.2W, 0402", Digikey Part Number=541-0.0YBCT-ND, Manufacturer="Vishay Dale", Mouser Part Number=71-CRCW04020000Z0EDH, Operating Temperature Range="-55°C to +155°C", Power_W=200mW
R3 R17: library part CMP-0018196-2, "RES, 30.0, 1%, 0.25 W, 1206", Manufacturer="Yageo America", Power_W=250mW, Supplier Part Number 1=311-30.0FRCT-ND, TempCo="100 ppm/C", Tolerance_%=1%, Value2=0.25W, Value_Code=30R0, ValueDisplayed=30.0
R4: library part CMP-0023013-5, "RES, 300, 1%, 0.1 W, 0603", Manufacturer=Yageo, Power_W=100mW, Supplier Part Number 1=311-300HRCT-ND, TempCo="100 ppm/C", Tolerance_%=1%, Value2=0.1W, Value_Code=300R, ValueDisplayed=300
R5: library part CMP-0018689-2, "RES, 4.7 k, 5%, 0.25 W, 1206", Manufacturer=Vishay-Dale, Power_W=250mW, Supplier Part Number 1=541-4.7KECT-ND, TempCo="200 ppm/C", Tolerance_%=5%, Value2=0.25W, Value_Code=4k70, ValueDisplayed=4.7k
R6: library part CMP-0022438-1, "RES, 47.0 k, 1%, 0.1 W, AEC-Q200 Grade 0, 0603", Manufacturer=Vishay-Dale, Power_W=100mW, Supplier Part Number 1=541-47.0KHCT-ND, TempCo="100 ppm/C", Tolerance_%=1%, Value2=0.1W, Value_Code=47k0, ValueDisplayed=47.0k
R7 R8: library part CMP-0026220-2, "RES, 28.7 k, 1%, 0.063 W, AEC-Q200 Grade 0, 0402", Manufacturer=Vishay-Dale, Power_W=63mW, Supplier Part Number 1=541-28.7KLCT-ND, TempCo="100 ppm/C", Tolerance_%=1%, Value2=0.063W, Value_Code=28k7, ValueDisplayed=28.7k
R10: library part CMP-0026329-2, "RES, 3.01 k, 1%, 0.063 W, AEC-Q200 Grade 0, 0402", Manufacturer=Vishay-Dale, Power_W=63mW, Supplier Part Number 1=541-3.01KLCT-ND, TempCo="100 ppm/C", Tolerance_%=1%, Value2=0.063W, Value_Code=3k01, ValueDisplayed=3.01k
R11: library part CMP-0024571-1, "RES, 105 k, 0.5%, 0.1 W, 0603", Manufacturer="Yageo America", Power_W=100mW, TempCo="50 ppm/C", Tolerance_%=0.5%, Value2=0.1W, Value_Code=105k
R14: library part CMP-0026027-3, "RES, 15.0 k, 1%, 0.063 W, AEC-Q200 Grade 0, 0402", Manufacturer=Vishay-Dale, Power_W=63mW, Supplier Part Number 1=541-15.0KLCT-ND, TempCo="100 ppm/C", Tolerance_%=1%, Value2=0.063W, Value_Code=15k0, ValueDisplayed=15.0k
R15: library part CMP-0026739-1, "RES, 4.70 k, 1%, 0.0625 W, 0402", Manufacturer="Yageo America", Power_W=62.5mW, Supplier Part Number 1=311-4.7KLRCT-ND, TempCo="100 ppm/C", Tolerance_%=1%, Value2=0.0625W, Value_Code=4k70, ValueDisplayed=4.70k
R16: library part CMP-0026866-2, "RES, 1.0, 5%, 0.063 W, 0402", Manufacturer=Vishay-Dale, Power_W=63mW, Supplier Part Number 1=541-1.0JCT-ND, TempCo="200 ppm/C", Tolerance_%=5%, Value2=0.063W, Value_Code=1R00, ValueDisplayed=1.0
R18: library part CMP-0026854-1, "RES, 1.2 k, 5%, 0.063 W, 0402", Manufacturer=Vishay-Dale, Power_W=63mW, Supplier Part Number 1=541-1.2KJCT-ND, TempCo="200 ppm/C", Tolerance_%=5%, Value2=0.063W, Value_Code=1k20, ValueDisplayed=1.2k
R19: library part CMP-0025557-3, "RES, 75.0 k, 0.5%, 0.1 W, 0603", Manufacturer="Yageo America", Power_W=100mW, TempCo="50 ppm/C", Tolerance_%=0.5%, Value2=0.1W, Value_Code=75k0, ValueDisplayed=75.0k
R21: library part CMP-0027008-4, "RES, 0, 5%, 0.05 W, 0201", Manufacturer=Vishay-Dale, Power_W=50mW, Supplier Part Number 1=72M6743, TempCo=ppm/C, Tolerance_%=5%, Value2=0.05W, Value_Code=0000, ValueDisplayed=0
R42: library part CMP-0025977-1, "RES, 11.5 k, 1%, 0.063 W, 0402", Manufacturer=Vishay-Dale, Power_W=63mW, Supplier Part Number 1=541-11.5KLCT-ND, TempCo="100 ppm/C", Tolerance_%=1%, Value2=0.063W, Value_Code=11k5, ValueDisplayed=11.5k
R43: library part CMP-0026201-1, "RES, 25.5 k, 1%, 0.063 W, 0402", Manufacturer=Vishay-Dale, Power_W=63mW, Supplier Part Number 1=541-25.5KLCT-ND, TempCo="100 ppm/C", Tolerance_%=1%, Value2=0.063W, Value_Code=25k5, ValueDisplayed=25.5k
R50: library part CMP-0025712-2, "RES, 12, 5%, 0.1 W, 0603", Manufacturer=Vishay-Dale, Power_W=100mW, Supplier Part Number 1=541-12GCT-ND, TempCo="200 ppm/C", Tolerance_%=5%, Value2=0.1W, Value_Code=12R0, ValueDisplayed=12
RT1: library part CMP-0002353-2, "Thermistor NTC, 100k ohm, 1%, 0402", Manufacturer=MuRata, Power_W=100mW, Tolerance_%=1%
T1: Manufacturer="Fort Electronics", PartNumber=ATQ23-14
U1: library part CMP-0086802-1, "FAST TURN-OFF INTELLIGENT RECTIF", Manufacturer="Monolithic Power Systems"
U2: library part CMP-0066199-1, "2.5V Low Iq Adjustable Precision Shunt Regulator, DBZ0003A (SOT-23-3)", Alternate Manufacturer="Texas Instruments"
U3: library part CMP-0006160-3, "Optocoupler, 5 kV, 63-125% CTR, SMT", Manufacturer=Vishay-Semiconductor, Supplier Part Number 1=VOL618A-2TCT-ND, Voltage_Isolation_Vrms=5kV
U8: library part CMP-0122264-1, Manufacturer="Texas Instruments", Operating Temperature Range=to

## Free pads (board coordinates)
  round 1.5 hole 1.1: 1(-1.305,-25.53) 1(1.71,-25.425)
  oval 2.2x2.4 hole 1.7: 5(-44.85,10.14) 5(-44.82,13.545)
  round 1.524 hole 0.762: 8(-9.09,9.645) 8(-8.226,16.463) 9(-37.995,15.9) 9(-37.95,12.825)
  rect 1.2x1.8 smd far side: N(-37.475,15.545) N(-37.455,12.892) N(-35.08,12.88) N(-35.065,15.535)
  rect 2.5x1 smd far side: N(-4.53,-0.06) N(0.072,-0.069)
  rect 2x2 smd far side: N(-4.515,-4.755) N(-0.3,-4.77)
  rect 2x2 smd: N(-4.515,-4.755) N(-0.285,-4.77)
  rect 2.5x1.2 smd far side: N(-4.515,2.295) N(0.045,2.31)

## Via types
v1: diameter 0.5, hole 0.25, Top Layer to Bottom Layer, 301 vias
v2: diameter 0.5, hole 0.25, Top Layer to Bottom Layer, tented both sides, 45 vias
v3: diameter 0.61, hole 0.203, Top Layer to Bottom Layer, tented both sides, 15 vias
v4: diameter 0.5, hole 0.3, Top Layer to Bottom Layer, tented both sides, 15 vias
v5: diameter 0.5, hole 0.2, Top Layer to Bottom Layer, tented both sides, 12 vias

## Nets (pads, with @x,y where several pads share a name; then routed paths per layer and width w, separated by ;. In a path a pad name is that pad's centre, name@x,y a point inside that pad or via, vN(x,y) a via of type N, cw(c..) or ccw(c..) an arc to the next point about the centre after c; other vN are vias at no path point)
APGND: C16.2 NT1.2 R7.1 R8.1 R42.1 R43.1 RT1.1 U3.3 U8.10 | length 2
  Bottom Layer w0.254: U3.3@-24.905,25.41 -23.012,25.41 R42.1@-22.93,25.328
FB_ACDC: pad.N@-35.065,15.535 R2.1 R16.2 | length 17.7
  Top Layer w0.254: v3(-43.35,20.55) -43.278,20.55 -42.558,21.27 v3@-35.085,21.27 ; v4(-36.073,24.027) -36.073,22.258 v3@-35.085,21.27 ; v4(-35.008,20.622) -35.024,20.638 -35.024,21.209 v3(-35.04,21.225) v3@-35.085,21.27
  Bottom Layer w0.254: pad.N@-35.04,15.33 v4@-35.04,20.622
LINE: F1.2 pad.1@-1.305,-25.53 | length 7
  Top Layer w1.5: pad.1@-1.305,-25.53 -1.305,-22.1 F1.2@-1.24,-22.035
  Bottom Layer w1.5: pad.1@-1.305,-25.53 -1.24,-25.465 F1.2@-1.24,-22.035
NetC1_2: C1.2 F1.1 L2.4 | length 28.6
  Top Layer w1.5: F1.1@-6.24,-22.035 -6.24,-20.595 -5.055,-19.41 -5.055,-18.33 -6.33,-17.055 C1.2@-6.33,-16.785 -5.055,-16.785 -3.735,-15.465 -3.735,-13.08 -4.665,-12.15 L2.4@-6.19,-12.15
  Bottom Layer w1.5: C1.2@-6.33,-16.785 C1.2@-6.12,-16.785 ; F1.1@-6.24,-22.035 -5.115,-20.91 -5.115,-17.79 C1.2@-6.12,-16.785 ; L2.4@-6.19,-12.15 -4.8,-12.15 -3.9,-13.05 -3.9,-15.09 -5.595,-16.785 C1.2@-6.12,-16.785
NetC2_1: C2.1 C17.2 R9.1 R10.2 R11.2 | length 6.5
  Bottom Layer w0.254: C17.2@-40.29,18.87 -40.29,19.93 R11.2@-40.515,20.155 -40.515,20.18 -40.167,20.528 -39.596,20.528 -39.358,20.766 C2.1@-39.358,20.88 ; C17.2@-40.29,19.037 -40.163,19.164 -39.396,19.164 R9.1@-38.865,19.695 -38.809,19.639 -38.184,19.639 -37.927,19.382 R10.2@-37.125,19.382 R10.2@-37.091,19.348
NetC2_2: C2.2 R18.2 | length 1.1
  Bottom Layer w0.254: C2.2@-38.342,20.88 R18.2@-38.342,21.93
NetC3_1: C3.1 R1.1 R3.2 R17.2 | length 6.7
  Bottom Layer w0.8: R3.2@-26.401,11.339 -26.393,11.347 -24.298,11.347 -24.273,11.322 -22.283,11.322 -22.221,11.26 C3.1@-21.758,11.26 -21.752,11.255 -21.752,9.207 R1.1@-21.747,9.201
NetC3_2: C3.2 C9.1 C19.1 C22.1 C64.1 L1.2 R1.2 R5.2 T1.3 | length 44.2
  Top Layer w0.4: v3(-23.825,8.97) -23.785,9.01 -22.96,9.01 -22.205,9.765 -22.205,12.465 -20.94,13.73 -19.915,13.73 T1.3@-19.685,13.96
  Top Layer w1: C9.1@-14.913,14.699 -12.469,12.255 -5.84,12.255 -4.145,13.95 -4.145,21.139 -3.559,21.725 -0.801,21.725 L1.2@-0.725,21.801
  Top Layer w1.2: C64.1@-14.885,6.047 C9.1@-14.885,14.671
  Bottom Layer w0.5: L1.2@-0.725,21.801 -0.674,21.852 1.082,21.852 R5.2@1.133,21.902
  Bottom Layer w1.2: C3.2@-21.758,14.16 -19.608,14.16 -19.408,13.96 T1.3@-19.3,13.96
NetC8_1: C8.1 D1.1 L1.1 R5.1 | length 13.8
  Top Layer w1: C8.1@-6.361,22.464 -6.241,22.464 -5.384,23.321 -1.944,23.321 -1.164,24.101 -0.925,24.101 L1.1@-0.725,24.301
  Bottom Layer w0.5: L1.1@-0.725,24.301 -0.474,24.552 0.882,24.552 R5.1@1.133,24.802
  Bottom Layer w1: C8.1@-6.225,21.66 -6.225,19.74 -5.48,18.995 -5.48,17.505 D1.1@-4.83,16.855
NetC13_2: C13.2 R50.2 | length 0.9
  Bottom Layer w0.5: C13.2@-41.25,10.125 -41.242,10.132 -40.407,10.132 R50.2@-40.4,10.14
NetC14_1: C14.1 U1.4 | length 1.3
  Bottom Layer w0.254: C14.1@-38.009,1.223 -37.886,1.1 -37.886,1.058 -37.882,1.055 U1.4@-36.798,1.055
NetC15_1: C15.1 U8.11 | length 2
  Bottom Layer w0.254: U8.11@-19.198,23.13 -19.197,23.774 C15.1@-18.26,24.712
NetC16_1: C16.1 R12.1 U8.5 | length 5.1
  Top Layer w0.254: v3(-24.361,20.94) -24.29,20.94 -24.035,21.195 -22.021,21.195 v3(-21.961,21.255)
  Bottom Layer w0.254: R12.1@-25.108,20.932 -25.103,20.936 -24.366,20.936 v3(-24.361,20.94) ; C16.1@-22.51,21.186 -22.476,21.22 -21.996,21.22 v3(-21.961,21.255) -21.893,21.323 -21.525,21.323 -21.345,21.503 U8.5@-20.848,21.505 U8.5@-20.848,21.505
NetC20_1: C20.1 R15.1 | length 0.9
  Bottom Layer w0.254: R15.1@-39.677,23.205 -39.662,23.19 -39.632,23.19 -39.609,23.214 -39.609,23.978 C20.1@-39.585,24.002
NetC20_2: C20.2 C21.2 C222.2 R2.2 R14.1 U2.1 U3.2 | length 7.9
  Bottom Layer w0.254: C20.2@-39.585,25.018 -39.615,25.048 -40.869,25.048 -40.952,25.131 -41.667,25.131 U2.1@-41.678,25.141 ; C20.2@-39.471,25.018 R14.1@-38.565,25.018 -38.502,25.081 -37.302,25.081 C222.2@-37.275,25.108 ; C222.2@-37.273,25.11 R2.2@-36.075,25.11 -34.86,25.11 U3.2@-34.572,25.398 ; U2.1@-41.833,25.296 U2.1@-41.678,25.141 ; U2.1@-41.833,25.296 U2.1@-41.678,25.141 ; U2.1@-41.833,25.296 U2.1@-41.678,25.141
